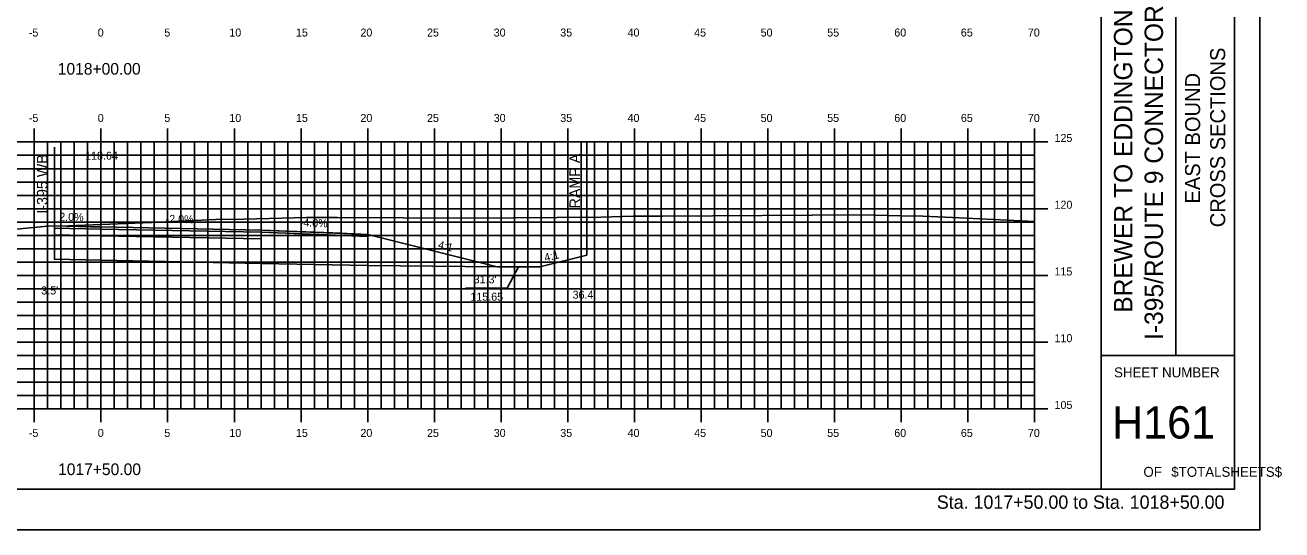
# Model space of a CAD drawing. Extents: x 853512 to 853684, y 365624 to 365734.
# Drawn here: x 853589.9 to 853684.1, y 365624 to 365661.8 of the extents above; entities that cross this region are included whole.
import ezdxf

# ---------------------------------------------------------------- set-up
doc = ezdxf.new("R2010")
doc.units = 0
for name, color, linetype in [('ANNOTATION', 7, 'Continuous'), ('BORDER', 7, 'Continuous'), ('D_Roadway_Centerline', 7, 'Continuous'), ('D_Roadway_Centerline_Text', 7, 'Continuous'), ('D_Roadway_Edge_Shoulder', 7, 'Continuous'), ('D_Roadway_Edge_TW', 7, 'Continuous'), ('D_Roadway_FinishedGrade', 7, 'Continuous'), ('D_Roadway_Pavement', 7, 'Continuous'), ('D_Roadway_SubGrade', 7, 'Continuous'), ('D_Text_Standard', 7, 'Continuous'), ('Default', 7, 'Continuous'), ('H_V ANNOTATION', 7, 'Continuous'), ('M_Roadway_Centerline', 7, 'Continuous'), ('MAJOR', 7, 'Continuous'), ('MINOR', 7, 'Continuous'), ('PLOT BOUNDARY', 7, 'Continuous'), ('S_Roadway_Centerline', 7, 'Continuous')]:
    doc.layers.add(name, color=color, linetype=linetype)

msp = doc.modelspace()

# ---------------------------------------------------------------- linework, layer by layer
at = {"layer": 'ANNOTATION'}
msp.add_lwpolyline([(853622.911, 365642.072), (853626.021, 365642.072), (853626.886, 365643.677)], dxfattribs=at)
at = {"layer": 'BORDER'}
for p, q in [((853670.575, 365627.027), (853670.575, 365732.027)), ((853676.166, 365637.03), (853676.166, 365672.03)), ((853670.575, 365637.03), (853680.575, 365637.03))]:
    msp.add_line(p, q, dxfattribs=at)
msp.add_lwpolyline([(853520.575, 365627.027), (853680.575, 365627.027), (853680.575, 365732.027), (853520.575, 365732.027)], close=True, dxfattribs=at)
at = {"layer": 'D_Roadway_Centerline'}
for p, q in [((853615.574, 365643.766), (853625.29, 365643.677)), ((853625.29, 365643.677), (853628.481, 365643.677))]:
    msp.add_line(p, q, dxfattribs=at)
for points in [[(853592.079, 365646.736), (853592.081, 365646.736), (853594.792, 365646.681), (853595.575, 365646.666), (853607.573, 365646.426), (853607.575, 365646.426), (853612.97, 365646.21), (853615.574, 365646.106)], [(853615.574, 365646.106), (853619.574, 365645.106), (853625.29, 365643.677)], [(853628.481, 365643.677), (853632.01, 365644.554)]]:
    msp.add_lwpolyline(points, dxfattribs=at)
at = {"layer": 'D_Roadway_Edge_Shoulder'}
for points in [[(853595.575, 365646.666), (853592.079, 365646.736), (853592.079, 365646.57), (853595.575, 365646.5)], [(853607.575, 365646.426), (853615.574, 365646.106), (853615.574, 365645.94), (853607.575, 365646.26)]]:
    msp.add_lwpolyline(points, close=True, dxfattribs=at)
at = {"layer": 'D_Roadway_Edge_TW'}
msp.add_lwpolyline([(853595.575, 365646.666), (853607.575, 365646.426), (853607.575, 365646.26), (853595.575, 365646.5)], close=True, dxfattribs=at)
msp.add_lwpolyline([(853607.575, 365646.426), (853607.575, 365646.26)], dxfattribs=at)
at = {"layer": 'D_Roadway_FinishedGrade'}
for p, q in [((853592.079, 365646.736), (853592.079, 365646.486)), ((853595.575, 365646.666), (853595.575, 365646.416)), ((853607.575, 365646.426), (853607.575, 365646.176)), ((853615.574, 365646.106), (853615.574, 365645.856))]:
    msp.add_line(p, q, dxfattribs=at)
at = {"layer": 'D_Roadway_Pavement'}
for points in [[(853595.575, 365646.5), (853592.079, 365646.57), (853592.079, 365646.07), (853595.575, 365646)], [(853595.575, 365646.5), (853607.575, 365646.26), (853607.575, 365645.76), (853595.575, 365646)]]:
    msp.add_lwpolyline(points, close=True, dxfattribs=at)
msp.add_lwpolyline([(853607.575, 365646.26), (853607.575, 365645.76)], dxfattribs=at)
msp.add_lwpolyline([(853607.575, 365646.26), (853607.575, 365645.76)], dxfattribs=at)
at = {"layer": 'D_Roadway_SubGrade'}
for p, q in [((853592.079, 365652.64), (853592.079, 365644.236)), ((853632.01, 365652.961), (853632.01, 365644.554))]:
    msp.add_line(p, q, dxfattribs=at)
for points in [[(853595.575, 365646), (853592.079, 365646.07), (853592.079, 365646.57), (853592.079, 365646.736), (853592.079, 365644.236), (853595.575, 365644.166)], [(853595.575, 365646), (853607.575, 365645.76), (853607.575, 365643.926), (853595.575, 365644.166)], [(853607.575, 365645.76), (853607.575, 365646.26), (853615.574, 365645.94), (853615.574, 365646.106), (853615.574, 365643.766), (853607.575, 365643.926)]]:
    msp.add_lwpolyline(points, close=True, dxfattribs=at)
msp.add_lwpolyline([(853607.575, 365645.76), (853607.575, 365643.926)], dxfattribs=at)
at = {"layer": 'Default'}
msp.add_lwpolyline([(853615.574, 365646.106), (853619.574, 365645.106), (853625.29, 365643.677)], dxfattribs=at)
at = {"layer": 'MAJOR'}
for p, q in [((853590.575, 365654.029), (853590.575, 365653.027)), ((853595.575, 365654.029), (853595.575, 365653.027)), ((853600.575, 365654.029), (853600.575, 365653.027)), ((853605.575, 365654.029), (853605.575, 365653.027)), ((853610.575, 365654.029), (853610.575, 365653.027)), ((853615.575, 365654.029), (853615.575, 365653.027)), ((853620.575, 365654.029), (853620.575, 365653.027)), ((853625.575, 365654.029), (853625.575, 365653.027)), ((853630.575, 365654.029), (853630.575, 365653.027)), ((853635.575, 365654.029), (853635.575, 365653.027)), ((853640.575, 365654.029), (853640.575, 365653.027)), ((853645.575, 365654.029), (853645.575, 365653.027)), ((853650.575, 365654.029), (853650.575, 365653.027)), ((853655.575, 365654.029), (853655.575, 365653.027)), ((853660.575, 365654.029), (853660.575, 365653.027)), ((853665.575, 365654.029), (853665.575, 365653.027)), ((853525.575, 365653.027), (853665.575, 365653.027)), ((853525.575, 365653.027), (853665.575, 365653.027)), ((853590.575, 365633.027), (853590.575, 365653.027)), ((853595.575, 365633.027), (853595.575, 365653.027)), ((853600.575, 365633.027), (853600.575, 365653.027)), ((853605.575, 365633.027), (853605.575, 365653.027)), ((853610.575, 365633.027), (853610.575, 365653.027)), ((853615.575, 365633.027), (853615.575, 365653.027)), ((853620.575, 365633.027), (853620.575, 365653.027)), ((853625.575, 365633.027), (853625.575, 365653.027)), ((853630.575, 365633.027), (853630.575, 365653.027)), ((853635.575, 365633.027), (853635.575, 365653.027)), ((853640.575, 365633.027), (853640.575, 365653.027)), ((853645.575, 365633.027), (853645.575, 365653.027)), ((853650.575, 365633.027), (853650.575, 365653.027)), ((853655.575, 365633.027), (853655.575, 365653.027)), ((853660.575, 365633.027), (853660.575, 365653.027)), ((853666.577, 365653.027), (853664.573, 365653.027)), ((853665.575, 365633.027), (853665.575, 365653.027)), ((853665.575, 365633.027), (853665.575, 365653.027)), ((853525.575, 365648.027), (853665.575, 365648.027)), ((853666.577, 365648.027), (853664.573, 365648.027)), ((853525.575, 365643.027), (853665.575, 365643.027)), ((853666.577, 365643.027), (853664.573, 365643.027)), ((853525.575, 365638.027), (853665.575, 365638.027)), ((853666.577, 365638.027), (853664.573, 365638.027)), ((853525.575, 365633.027), (853665.575, 365633.027)), ((853525.575, 365633.027), (853665.575, 365633.027)), ((853590.575, 365632.025), (853590.575, 365633.027)), ((853595.575, 365632.025), (853595.575, 365633.027)), ((853600.575, 365632.025), (853600.575, 365633.027)), ((853605.575, 365632.025), (853605.575, 365633.027)), ((853610.575, 365632.025), (853610.575, 365633.027)), ((853615.575, 365632.025), (853615.575, 365633.027)), ((853620.575, 365632.025), (853620.575, 365633.027)), ((853625.575, 365632.025), (853625.575, 365633.027)), ((853630.575, 365632.025), (853630.575, 365633.027)), ((853635.575, 365632.025), (853635.575, 365633.027)), ((853640.575, 365632.025), (853640.575, 365633.027)), ((853645.575, 365632.025), (853645.575, 365633.027)), ((853650.575, 365632.025), (853650.575, 365633.027)), ((853655.575, 365632.025), (853655.575, 365633.027)), ((853660.575, 365632.025), (853660.575, 365633.027)), ((853666.577, 365633.027), (853664.573, 365633.027)), ((853665.575, 365632.025), (853665.575, 365633.027))]:
    msp.add_line(p, q, dxfattribs=at)
at = {"layer": 'MINOR'}
for p, q in [((853591.575, 365633.027), (853591.575, 365653.027)), ((853592.575, 365633.027), (853592.575, 365653.027)), ((853593.575, 365633.027), (853593.575, 365653.027)), ((853594.575, 365633.027), (853594.575, 365653.027)), ((853596.575, 365633.027), (853596.575, 365653.027)), ((853597.575, 365633.027), (853597.575, 365653.027)), ((853598.575, 365633.027), (853598.575, 365653.027)), ((853599.575, 365633.027), (853599.575, 365653.027)), ((853601.575, 365633.027), (853601.575, 365653.027)), ((853602.575, 365633.027), (853602.575, 365653.027)), ((853603.575, 365633.027), (853603.575, 365653.027)), ((853604.575, 365633.027), (853604.575, 365653.027)), ((853606.575, 365633.027), (853606.575, 365653.027)), ((853607.575, 365633.027), (853607.575, 365653.027)), ((853608.575, 365633.027), (853608.575, 365653.027)), ((853609.575, 365633.027), (853609.575, 365653.027)), ((853611.575, 365633.027), (853611.575, 365653.027)), ((853612.575, 365633.027), (853612.575, 365653.027)), ((853613.575, 365633.027), (853613.575, 365653.027)), ((853614.575, 365633.027), (853614.575, 365653.027)), ((853616.575, 365633.027), (853616.575, 365653.027)), ((853617.575, 365633.027), (853617.575, 365653.027)), ((853618.575, 365633.027), (853618.575, 365653.027)), ((853619.575, 365633.027), (853619.575, 365653.027)), ((853621.575, 365633.027), (853621.575, 365653.027)), ((853622.575, 365633.027), (853622.575, 365653.027)), ((853623.575, 365633.027), (853623.575, 365653.027)), ((853624.575, 365633.027), (853624.575, 365653.027)), ((853626.575, 365633.027), (853626.575, 365653.027)), ((853627.575, 365633.027), (853627.575, 365653.027)), ((853628.575, 365633.027), (853628.575, 365653.027)), ((853629.575, 365633.027), (853629.575, 365653.027)), ((853631.575, 365633.027), (853631.575, 365653.027)), ((853632.575, 365633.027), (853632.575, 365653.027)), ((853633.575, 365633.027), (853633.575, 365653.027)), ((853634.575, 365633.027), (853634.575, 365653.027)), ((853636.575, 365633.027), (853636.575, 365653.027)), ((853637.575, 365633.027), (853637.575, 365653.027)), ((853638.575, 365633.027), (853638.575, 365653.027)), ((853639.575, 365633.027), (853639.575, 365653.027)), ((853641.575, 365633.027), (853641.575, 365653.027)), ((853642.575, 365633.027), (853642.575, 365653.027)), ((853643.575, 365633.027), (853643.575, 365653.027)), ((853644.575, 365633.027), (853644.575, 365653.027)), ((853646.575, 365633.027), (853646.575, 365653.027)), ((853647.575, 365633.027), (853647.575, 365653.027)), ((853648.575, 365633.027), (853648.575, 365653.027)), ((853649.575, 365633.027), (853649.575, 365653.027)), ((853651.575, 365633.027), (853651.575, 365653.027)), ((853652.575, 365633.027), (853652.575, 365653.027)), ((853653.575, 365633.027), (853653.575, 365653.027)), ((853654.575, 365633.027), (853654.575, 365653.027)), ((853656.575, 365633.027), (853656.575, 365653.027)), ((853657.575, 365633.027), (853657.575, 365653.027)), ((853658.575, 365633.027), (853658.575, 365653.027)), ((853659.575, 365633.027), (853659.575, 365653.027)), ((853661.575, 365633.027), (853661.575, 365653.027)), ((853662.575, 365633.027), (853662.575, 365653.027)), ((853663.575, 365633.027), (853663.575, 365653.027)), ((853664.575, 365633.027), (853664.575, 365653.027)), ((853525.575, 365652.027), (853665.575, 365652.027)), ((853665.575, 365652.027), (853664.573, 365652.027)), ((853525.575, 365651.027), (853665.575, 365651.027)), ((853665.575, 365651.027), (853664.573, 365651.027)), ((853525.575, 365650.027), (853665.575, 365650.027)), ((853665.575, 365650.027), (853664.573, 365650.027)), ((853525.575, 365649.027), (853665.575, 365649.027)), ((853665.575, 365649.027), (853664.573, 365649.027)), ((853525.575, 365647.027), (853665.575, 365647.027)), ((853665.575, 365647.027), (853664.573, 365647.027)), ((853525.575, 365646.027), (853665.575, 365646.027)), ((853665.575, 365646.027), (853664.573, 365646.027)), ((853525.575, 365645.027), (853665.575, 365645.027)), ((853665.575, 365645.027), (853664.573, 365645.027)), ((853525.575, 365644.027), (853665.575, 365644.027)), ((853665.575, 365644.027), (853664.573, 365644.027)), ((853525.575, 365642.027), (853665.575, 365642.027)), ((853665.575, 365642.027), (853664.573, 365642.027)), ((853525.575, 365641.027), (853665.575, 365641.027)), ((853665.575, 365641.027), (853664.573, 365641.027)), ((853525.575, 365640.027), (853665.575, 365640.027)), ((853665.575, 365640.027), (853664.573, 365640.027)), ((853525.575, 365639.027), (853665.575, 365639.027)), ((853665.575, 365639.027), (853664.573, 365639.027)), ((853525.575, 365637.027), (853665.575, 365637.027)), ((853665.575, 365637.027), (853664.573, 365637.027)), ((853525.575, 365636.027), (853665.575, 365636.027)), ((853665.575, 365636.027), (853664.573, 365636.027)), ((853525.575, 365635.027), (853665.575, 365635.027)), ((853665.575, 365635.027), (853664.573, 365635.027)), ((853525.575, 365634.027), (853665.575, 365634.027)), ((853665.575, 365634.027), (853664.573, 365634.027))]:
    msp.add_line(p, q, dxfattribs=at)
at = {"layer": 'PLOT BOUNDARY'}
msp.add_lwpolyline([(853512.481, 365623.968), (853682.481, 365623.968), (853682.481, 365733.968), (853512.481, 365733.968)], close=True, dxfattribs=at)
at = {"layer": 'S_Roadway_Centerline'}
msp.add_lwpolyline([(853581.032, 365645.7), (853591.548, 365646.72), (853593.117, 365646.744), (853599.355, 365646.996), (853599.872, 365647.028), (853604.189, 365647.231), (853606.307, 365647.253), (853610.987, 365647.372), (853613.273, 365647.37), (853623.18, 365647.312), (853633.086, 365647.403), (853635.469, 365647.462), (853637.695, 365647.475), (853652.63, 365647.574), (853656.528, 365647.466), (853656.643, 365647.491), (853659.43, 365647.379), (853665.575, 365647.061)], dxfattribs=at)

# ---------------------------------------------------------------- texts
at = {"layer": 'ANNOTATION'}
for s, height, rotation, p in [('RAMP A', 0.8, 90, (853631.504, 365648.049)), ('I-395 WB', 0.8, 90, (853591.573, 365647.654)), ('2.0%', 0.6, 358.85259, (853592.44, 365647.129)), ('-2.0%', 0.6, 358.85423, (853600.417, 365646.969)), ('-4.0%', 0.6, 357.70931, (853610.47, 365646.711)), ('4:1', 0.6, 345.96376, (853620.803, 365645.074)), ('4:1', 0.6, 13.95836, (853628.891, 365644.054)), ("31.3' ", 0.6, 360, (853623.52, 365642.435)), ('115.65', 0.6, 360, (853623.273, 365641.135))]:
    msp.add_text(s, height=height, rotation=rotation, dxfattribs=at).set_placement(p)
at = {"layer": 'BORDER'}
for s, height, p in [('BREWER TO EDDINGTON', 1.37787, (853672.908, 365640.231)), ('I-395/ROUTE 9 CONNECTOR', 1.37787, (853675.209, 365638.192)), ('CROSS SECTIONS', 1.125, (853679.872, 365646.638)), ('EAST BOUND', 1.125, (853677.993, 365648.418))]:
    msp.add_text(s, height=height, rotation=90, dxfattribs=at).set_placement(p)
for s, height, p in [('SHEET NUMBER', 0.74527, (853671.54, 365635.393)), ('H161', 2.4194, (853671.386, 365630.809)), ('OF', 0.7453, (853673.742, 365627.94)), ('$TOTALSHEETS$', 0.74527, (853675.831, 365627.94))]:
    msp.add_text(s, height=height, dxfattribs=at).set_placement(p)
at = {"layer": 'D_Roadway_Centerline'}
for s, p in [('C', (853595.569, 365646.666)), ('L', (853595.575, 365646.658))]:
    msp.add_text(s, height=0.0146, dxfattribs=at).set_placement(p)
at = {"layer": 'D_Roadway_Centerline_Text'}
msp.add_text('118.64', height=0.6, dxfattribs=at).set_placement((853594.387, 365651.698))
at = {"layer": 'D_Text_Standard'}
for s, p in [("3.5'", (853591.098, 365641.601)), ("36.4'", (853630.938, 365641.284))]:
    msp.add_text(s, height=0.6, dxfattribs=at).set_placement(p)
at = {"layer": 'H_V ANNOTATION'}
for s, height, p in [('-5', 0.6, (853590.165, 365660.927)), ('0', 0.6, (853595.334, 365660.927)), ('5', 0.6, (853600.326, 365660.927)), ('10', 0.6, (853605.2, 365660.927)), ('15', 0.6, (853610.192, 365660.927)), ('20', 0.6, (853615.029, 365660.927)), ('25', 0.6, (853620.021, 365660.927)), ('30', 0.6, (853625.023, 365660.927)), ('35', 0.6, (853630.015, 365660.927)), ('40', 0.6, (853635.061, 365660.927)), ('45', 0.6, (853640.053, 365660.927)), ('50', 0.6, (853645.039, 365660.927)), ('55', 0.6, (853650.031, 365660.927)), ('60', 0.6, (853655.061, 365660.927)), ('65', 0.6, (853660.053, 365660.927)), ('70', 0.6, (853665.077, 365660.927)), ('1018+00.00', 0.875, (853592.336, 365658.07)), ('-5', 0.6, (853590.165, 365654.527)), ('0', 0.6, (853595.334, 365654.527)), ('5', 0.6, (853600.326, 365654.527)), ('10', 0.6, (853605.2, 365654.527)), ('15', 0.6, (853610.192, 365654.527)), ('20', 0.6, (853615.029, 365654.527)), ('25', 0.6, (853620.021, 365654.527)), ('30', 0.6, (853625.023, 365654.527)), ('35', 0.6, (853630.015, 365654.527)), ('40', 0.6, (853635.061, 365654.527)), ('45', 0.6, (853640.053, 365654.527)), ('50', 0.6, (853645.039, 365654.527)), ('55', 0.6, (853650.031, 365654.527)), ('60', 0.6, (853655.061, 365654.527)), ('65', 0.6, (853660.053, 365654.527)), ('70', 0.6, (853665.077, 365654.527)), ('125', 0.6, (853667.075, 365653.027)), ('120', 0.6, (853667.075, 365648.027)), ('115', 0.6, (853667.075, 365643.027)), ('110', 0.6, (853667.075, 365638.027)), ('105', 0.6, (853667.075, 365633.027)), ('-5', 0.6, (853590.165, 365630.927)), ('0', 0.6, (853595.334, 365630.927)), ('5', 0.6, (853600.326, 365630.927)), ('10', 0.6, (853605.2, 365630.927)), ('15', 0.6, (853610.192, 365630.927)), ('20', 0.6, (853615.029, 365630.927)), ('25', 0.6, (853620.021, 365630.927)), ('30', 0.6, (853625.023, 365630.927)), ('35', 0.6, (853630.015, 365630.927)), ('40', 0.6, (853635.061, 365630.927)), ('45', 0.6, (853640.053, 365630.927)), ('50', 0.6, (853645.039, 365630.927)), ('55', 0.6, (853650.031, 365630.927)), ('60', 0.6, (853655.061, 365630.927)), ('65', 0.6, (853660.053, 365630.927)), ('70', 0.6, (853665.077, 365630.927)), ('1017+50.00', 0.875, (853592.36, 365628.07)), ('Sta. 1017+50.00 to Sta. 1018+50.00', 1.0002, (853658.251, 365625.547))]:
    msp.add_text(s, height=height, dxfattribs=at).set_placement(p)
at = {"layer": 'M_Roadway_Centerline'}
for s, p in [('C', (853656.638, 365647.491)), ('L', (853656.643, 365647.484)), ('C', (853604.184, 365647.231)), ('L', (853604.189, 365647.224))]:
    msp.add_text(s, height=0.0146, dxfattribs=at).set_placement(p)

doc.saveas('drawing.dxf')
